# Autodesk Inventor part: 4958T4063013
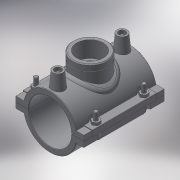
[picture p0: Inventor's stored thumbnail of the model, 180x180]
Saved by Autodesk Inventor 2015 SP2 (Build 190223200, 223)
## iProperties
Created: 2017-07
Part Number: 4958T4063013
Material: Generic
Description: PLASSON SADDLE 63X1.1/4" FEMALE BSPP
Document SubType Name: Modeling
Designer: KIM
Density: 1 g/cm^3
Appearance: Default
Author: KIM
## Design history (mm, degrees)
derived "4958T4.ipt"
feature "Solid1::4958T4.ipt"
tag "TaggingFeature1"
body "Solid1"
other parameters: "d0" = 63, "d1" = 78.75, "d3" = 15.75, "d4" = 118, "d5" = 0, "d6" = 0.1, "d8" = 0, "d19" = 6, "d20" = 6, "d21" = 70.8, "d23" = 0, "d24" = 35.4, "d26" = 0, "d27" = 3, "d28" = 3, "d29" = 3, "d30" = 24.00694, "d31" = 6, "d32" = 0, "d33" = 0, "d34" = 0.6, "d40" = 42.21, "d41" = 63, "d43" = 0, "d45" = 0, "d46" = 6.3, "d47" = 61.5, "d48" = 50.6376, "d50" = 0, "d51" = 38.952, "d52" = 24, "d53" = 0, "d54" = 31.1616, "d56" = 0, "d57" = -9, "d58" = 0.5, "d59" = 0.1, "d60" = 0, "d61" = 0.5, "d64" = 1.16856, "d67" = 0.63, "d70" = 15, "d72" = 0, "d73" = 6, "d75" = 5, "d76" = 0, "d77" = 3.15, "d78" = 60.5, "d79" = 15, "d80" = 47.2, "d82" = 5 deg, "d84" = 4, "d85" = 14, "d86" = 0, "d87" = 3, "d88" = 0, "d89" = 1, "d90" = 1, "d91" = 94.4, "d92" = 0, "d93" = 0.5, "d94" = 33.15789, "d_" = 63, "Rp_" = 38.952, "L_" = 118, "d_t" = 6
